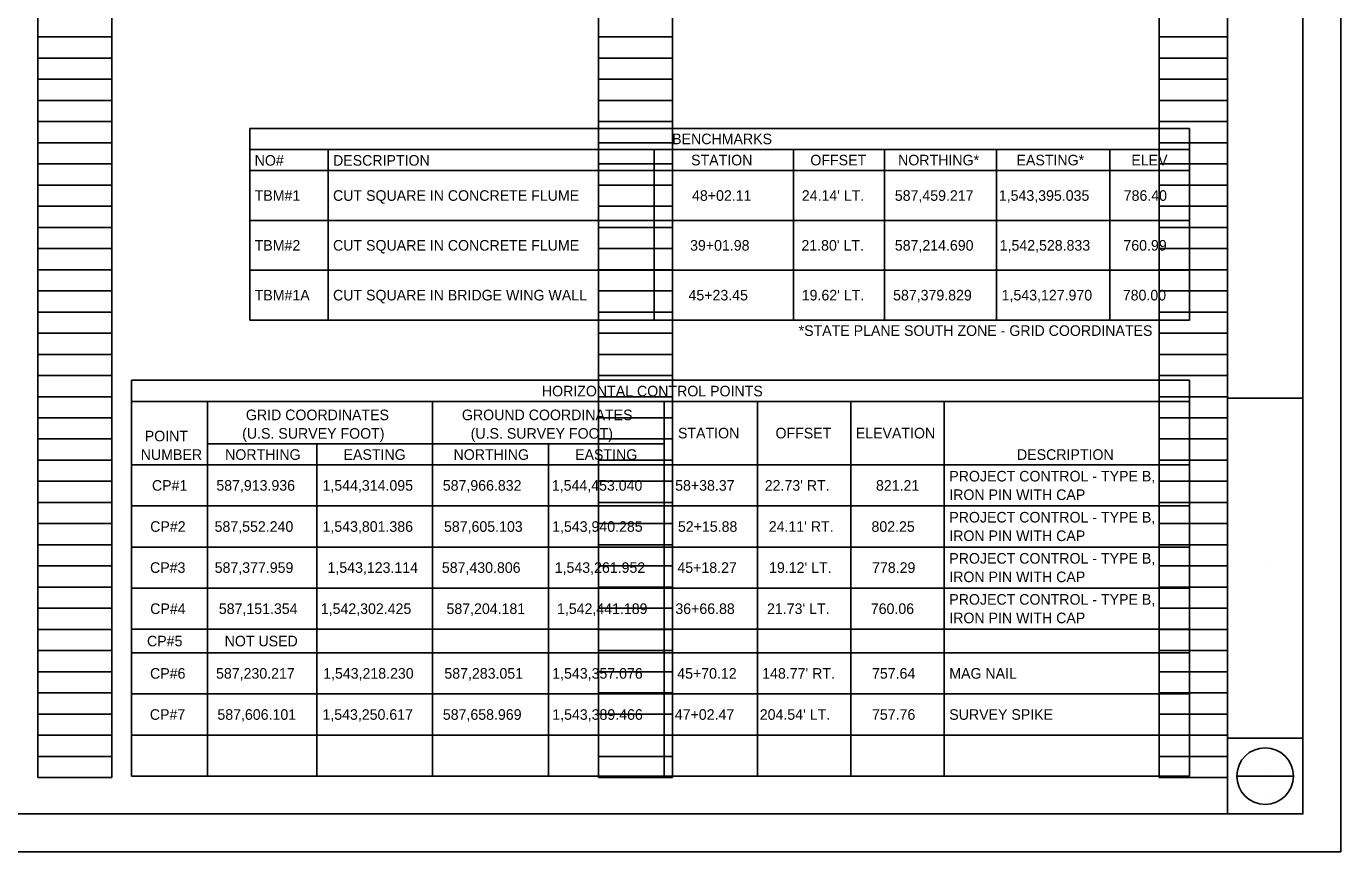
# Model space of a CAD drawing. Extents: x 0 to 34, y 0 to 22.
# Drawn here: x 16.61 to 34, y 0 to 10.92 of the extents above; entities that cross this region are included whole.
import ezdxf

# ---------------------------------------------------------------- set-up
doc = ezdxf.new("R2010")
doc.units = 0
for name, color, linetype in [('SH_Border', 7, 'Continuous'), ('SH_Cut_Line', 7, 'Continuous'), ('SH_Data', 7, 'Continuous'), ('SH_Text', 7, 'Continuous')]:
    doc.layers.add(name, color=color, linetype=linetype)

msp = doc.modelspace()

# ---------------------------------------------------------------- linework, layer by layer
at = {"layer": 'SH_Border'}
for p, q in [((32.5, 0.5), (32.5, 21.5)), ((32.5, 6), (33.5, 6)), ((32.5, 1.5), (33.5, 1.5))]:
    msp.add_line(p, q, dxfattribs=at)
msp.add_lwpolyline([(2, 21.5), (33.5, 21.5), (33.5, 0.5), (2, 0.5)], close=True, dxfattribs=at)
at = {"layer": 'SH_Cut_Line'}
msp.add_lwpolyline([(0, 0), (34, 0), (34, 22), (0, 22)], close=True, dxfattribs=at)
at = {"layer": 'SH_Data'}
for p, q in [((16.76, 0.98), (16.76, 21.14)), ((17.74, 0.98), (17.74, 21.14)), ((24.18, 0.98), (24.18, 21.14)), ((25.16, 0.98), (25.16, 21.14)), ((31.6, 0.98), (31.6, 21.14)), ((32.5, 0.98), (32.5, 21.14)), ((16.76, 10.78), (17.74, 10.78)), ((24.18, 10.78), (25.16, 10.78)), ((31.6, 10.78), (32.5, 10.78)), ((16.76, 10.5), (17.74, 10.5)), ((24.18, 10.5), (25.16, 10.5)), ((31.6, 10.5), (32.5, 10.5)), ((16.76, 10.22), (17.74, 10.22)), ((24.18, 10.22), (25.16, 10.22)), ((31.6, 10.22), (32.5, 10.22)), ((16.76, 9.94), (17.74, 9.94)), ((24.18, 9.94), (25.16, 9.94)), ((31.6, 9.94), (32.5, 9.94)), ((16.76, 9.66), (17.74, 9.66)), ((19.565, 9.57), (32, 9.57)), ((19.565, 9.57), (19.565, 7.034)), ((24.18, 9.66), (25.16, 9.66)), ((31.6, 9.66), (32.5, 9.66)), ((32, 9.57), (32, 7.034)), ((16.76, 9.38), (17.74, 9.38)), ((19.565, 9.29), (32, 9.29)), ((20.602, 9.29), (20.602, 7.034)), ((24.18, 9.38), (25.16, 9.38)), ((24.918, 9.29), (24.918, 7.034)), ((26.762, 9.29), (26.762, 7.034)), ((27.965, 9.29), (27.965, 7.034)), ((29.447, 9.29), (29.447, 7.034)), ((30.946, 9.29), (30.946, 7.034)), ((31.6, 9.38), (32.5, 9.38)), ((16.76, 9.1), (17.74, 9.1)), ((24.18, 9.1), (25.16, 9.1)), ((31.6, 9.1), (32.5, 9.1)), ((19.565, 9.01), (32, 9.01)), ((16.76, 8.82), (17.74, 8.82)), ((24.18, 8.82), (25.16, 8.82)), ((31.6, 8.82), (32.5, 8.82)), ((16.76, 8.54), (17.74, 8.54)), ((24.18, 8.54), (25.16, 8.54)), ((31.6, 8.54), (32.5, 8.54)), ((19.565, 8.352), (32, 8.352)), ((16.76, 8.26), (17.74, 8.26)), ((24.18, 8.26), (25.16, 8.26)), ((31.6, 8.26), (32.5, 8.26)), ((16.76, 7.98), (17.74, 7.98)), ((24.18, 7.98), (25.16, 7.98)), ((31.6, 7.98), (32.5, 7.98)), ((16.76, 7.7), (17.74, 7.7)), ((19.565, 7.693), (32, 7.693)), ((24.18, 7.7), (25.16, 7.7)), ((31.6, 7.7), (32.5, 7.7)), ((16.76, 7.42), (17.74, 7.42)), ((24.18, 7.42), (25.16, 7.42)), ((31.6, 7.42), (32.5, 7.42)), ((16.76, 7.14), (17.74, 7.14)), ((24.18, 7.14), (25.16, 7.14)), ((31.6, 7.14), (32.5, 7.14)), ((19.565, 7.034), (32, 7.034)), ((16.76, 6.86), (17.74, 6.86)), ((24.18, 6.86), (25.16, 6.86)), ((31.6, 6.86), (32.5, 6.86)), ((16.76, 6.58), (17.74, 6.58)), ((24.18, 6.58), (25.16, 6.58)), ((31.6, 6.58), (32.5, 6.58)), ((16.76, 6.3), (17.74, 6.3)), ((24.18, 6.3), (25.16, 6.3)), ((31.6, 6.3), (32.5, 6.3)), ((18, 6.238), (32, 6.238)), ((18, 6.238), (18, 1)), ((32, 6.238), (32, 1)), ((16.76, 6.02), (17.74, 6.02)), ((18, 5.958), (32, 5.958)), ((19.005, 5.958), (19.005, 1)), ((21.986, 5.958), (21.986, 1)), ((24.18, 6.02), (25.16, 6.02)), ((25.049, 5.958), (25.049, 1)), ((26.285, 5.958), (26.285, 1)), ((27.52, 5.958), (27.52, 1)), ((28.755, 5.958), (28.755, 1)), ((31.6, 6.02), (32.5, 6.02)), ((16.76, 5.74), (17.74, 5.74)), ((24.18, 5.74), (25.16, 5.74)), ((31.6, 5.74), (32.5, 5.74)), ((16.76, 5.46), (17.74, 5.46)), ((19.005, 5.398), (25.049, 5.398)), ((20.454, 5.398), (20.454, 1)), ((23.518, 5.398), (23.518, 1)), ((24.18, 5.46), (25.16, 5.46)), ((31.6, 5.46), (32.5, 5.46)), ((16.76, 5.18), (17.74, 5.18)), ((18, 5.118), (32, 5.118)), ((24.18, 5.18), (25.16, 5.18)), ((31.6, 5.18), (32.5, 5.18)), ((16.76, 4.9), (17.74, 4.9)), ((24.18, 4.9), (25.16, 4.9)), ((31.6, 4.9), (32.5, 4.9)), ((16.76, 4.62), (17.74, 4.62)), ((18, 4.574), (32, 4.574)), ((24.18, 4.62), (25.16, 4.62)), ((31.6, 4.62), (32.5, 4.62)), ((16.76, 4.34), (17.74, 4.34)), ((24.18, 4.34), (25.16, 4.34)), ((31.6, 4.34), (32.5, 4.34)), ((16.76, 4.06), (17.74, 4.06)), ((18, 4.031), (32, 4.031)), ((24.18, 4.06), (25.16, 4.06)), ((31.6, 4.06), (32.5, 4.06)), ((16.76, 3.78), (17.74, 3.78)), ((24.18, 3.78), (25.16, 3.78)), ((31.6, 3.78), (32.5, 3.78)), ((33, 3.792), (33, 3.792)), ((16.76, 3.5), (17.74, 3.5)), ((18, 3.487), (32, 3.487)), ((24.18, 3.5), (25.16, 3.5)), ((31.6, 3.5), (32.5, 3.5)), ((16.76, 3.22), (17.74, 3.22)), ((24.18, 3.22), (25.16, 3.22)), ((31.6, 3.22), (32.5, 3.22)), ((16.76, 2.94), (17.74, 2.94)), ((18, 2.944), (32, 2.944)), ((24.18, 2.94), (25.16, 2.94)), ((31.6, 2.94), (32.5, 2.94)), ((16.76, 2.66), (17.74, 2.66)), ((18, 2.631), (32, 2.631)), ((24.18, 2.66), (25.16, 2.66)), ((31.6, 2.66), (32.5, 2.66)), ((16.76, 2.38), (17.74, 2.38)), ((24.18, 2.38), (25.16, 2.38)), ((31.6, 2.38), (32.5, 2.38)), ((16.76, 2.1), (17.74, 2.1)), ((18, 2.087), (32, 2.087)), ((24.18, 2.1), (25.16, 2.1)), ((31.6, 2.1), (32.5, 2.1)), ((16.76, 1.82), (17.74, 1.82)), ((24.18, 1.82), (25.16, 1.82)), ((31.6, 1.82), (32.5, 1.82)), ((16.76, 1.54), (17.74, 1.54)), ((18, 1.544), (32, 1.544)), ((24.18, 1.54), (25.16, 1.54)), ((31.6, 1.54), (32.5, 1.54)), ((16.76, 1.26), (17.74, 1.26)), ((24.18, 1.26), (25.16, 1.26)), ((31.6, 1.26), (32.5, 1.26)), ((33, 1.085), (33, 1.085)), ((16.76, 0.98), (17.74, 0.98)), ((18, 1), (32, 1)), ((24.18, 0.98), (25.16, 0.98)), ((31.6, 0.98), (32.5, 0.98)), ((32.625, 1), (33.375, 1)), ((33, 0.745), (33, 0.745))]:
    msp.add_line(p, q, dxfattribs=at)
msp.add_circle((33, 1), 0.375, dxfattribs=at)

# ---------------------------------------------------------------- texts
at = {"layer": 'SH_Text'}
for s, p in [('BENCHMARKS', (25.155, 9.36)), ('NO#', (19.631, 9.076)), ('DESCRIPTION', (20.668, 9.076)), ('STATION', (25.405, 9.08)), ('OFFSET', (26.983, 9.08)), ('NORTHING*', (28.144, 9.08)), ('EASTING*', (29.711, 9.08)), ('ELEV', (31.23, 9.08)), ('TBM#1', (19.631, 8.611)), ('CUT SQUARE IN CONCRETE FLUME', (20.668, 8.611)), ('48+02.11', (25.418, 8.611)), ("24.14' LT.", (26.87, 8.611)), ('587,459.217', (28.101, 8.611)), ('1,543,395.035', (29.477, 8.611)), ('786.40', (31.129, 8.611)), ('TBM#2', (19.631, 7.952)), ('CUT SQUARE IN CONCRETE FLUME', (20.668, 7.952)), ('39+01.98', (25.392, 7.952)), ("21.80' LT.", (26.865, 7.952)), ('587,214.690', (28.101, 7.952)), ('1,542,528.833', (29.488, 7.952)), ('760.99', (31.125, 7.952)), ('TBM#1A', (19.631, 7.293)), ('CUT SQUARE IN BRIDGE WING WALL', (20.668, 7.293)), ('45+23.45', (25.371, 7.293)), ("19.62' LT.", (26.869, 7.293)), ('587,379.829', (28.078, 7.293)), ('1,543,127.970', (29.514, 7.293)), ('780.00', (31.117, 7.293)), ('*STATE PLANE SOUTH ZONE - GRID COORDINATES', (26.828, 6.824)), ('HORIZONTAL CONTROL POINTS', (23.431, 6.024)), ('GRID COORDINATES', (19.515, 5.709)), ('GROUND COORDINATES', (22.373, 5.709)), ('POINT', (18.177, 5.429)), ('(U.S. SURVEY FOOT)', (19.466, 5.464)), ('(U.S. SURVEY FOOT)', (22.489, 5.464)), ('STATION', (25.232, 5.468)), ('OFFSET', (26.522, 5.468)), ('ELEVATION', (27.584, 5.468)), ('NUMBER', (18.124, 5.184)), ('NORTHING', (19.24, 5.184)), ('EASTING', (20.807, 5.184)), ('NORTHING', (22.262, 5.184)), ('EASTING', (23.871, 5.184)), ('DESCRIPTION', (29.717, 5.184)), ('CP#1', (18.272, 4.776)), ('587,913.936', (19.124, 4.776)), ('1,544,314.095', (20.529, 4.776)), ('587,966.832', (22.12, 4.776)), ('1,544,453.040', (23.563, 4.776)), ('58+38.37', (25.194, 4.776)), ("22.73' RT.", (26.38, 4.776)), ('821.21', (27.851, 4.776)), ('PROJECT CONTROL - TYPE B,', (28.821, 4.898)), ('IRON PIN WITH CAP', (28.821, 4.653)), ('CP#2', (18.249, 4.232)), ('587,552.240', (19.101, 4.232)), ('1,543,801.386', (20.529, 4.232)), ('587,605.103', (22.136, 4.232)), ('1,543,940.285', (23.567, 4.232)), ('52+15.88', (25.231, 4.232)), ("24.11' RT.", (26.433, 4.232)), ('802.25', (27.792, 4.232)), ('PROJECT CONTROL - TYPE B,', (28.821, 4.355)), ('IRON PIN WITH CAP', (28.821, 4.11)), ('CP#3', (18.247, 3.689)), ('587,377.959', (19.102, 3.689)), ('1,543,123.114', (20.595, 3.689)), ('587,430.806', (22.108, 3.689)), ('1,543,261.952', (23.601, 3.689)), ('45+18.27', (25.224, 3.689)), ("19.12' LT.", (26.437, 3.689)), ('778.29', (27.8, 3.689)), ('PROJECT CONTROL - TYPE B,', (28.821, 3.811)), ('IRON PIN WITH CAP', (28.821, 3.566)), ('PROJECT CONTROL - TYPE B,', (28.821, 3.268)), ('CP#4', (18.249, 3.145)), ('587,151.354', (19.157, 3.145)), ('1,542,302.425', (20.506, 3.145)), ('587,204.181', (22.169, 3.145)), ('1,542,441.189', (23.631, 3.145)), ('36+66.88', (25.197, 3.145)), ("21.73' LT.", (26.41, 3.145)), ('760.06', (27.783, 3.145)), ('IRON PIN WITH CAP', (28.821, 3.023)), ('CP#5 ', (18.207, 2.717)), ('NOT USED', (19.234, 2.717)), ('CP#6', (18.247, 2.289)), ('587,230.217', (19.12, 2.289)), ('1,543,218.230', (20.537, 2.289)), ('587,283.051', (22.141, 2.289)), ('1,543,357.076', (23.568, 2.289)), ('45+70.12', (25.222, 2.289)), ("148.77' RT.", (26.346, 2.289)), ('757.64', (27.799, 2.289)), ('MAG NAIL', (28.821, 2.289)), ('CP#7', (18.244, 1.745)), ('587,606.101', (19.138, 1.745)), ('1,543,250.617', (20.528, 1.745)), ('587,658.969', (22.121, 1.745)), ('1,543,389.466', (23.569, 1.745)), ('47+02.47', (25.19, 1.745)), ("204.54' LT.", (26.314, 1.745)), ('757.76', (27.799, 1.745)), ('SURVEY SPIKE', (28.821, 1.745))]:
    msp.add_text(s, height=0.14, dxfattribs=at).set_placement(p)

doc.saveas('drawing.dxf')
